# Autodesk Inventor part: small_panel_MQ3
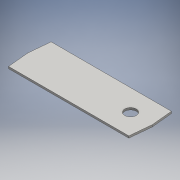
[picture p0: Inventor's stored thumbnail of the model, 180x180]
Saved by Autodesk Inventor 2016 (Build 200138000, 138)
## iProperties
Created: 2016-12
Part Number: small_panel_MQ3
Material: Типовые
Document SubType Name: Modeling
Designer: admin
Density: 1 g/cm^3
Appearance: По умолчанию
Author: admin
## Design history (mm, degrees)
sketch "Эскиз1"
  geometry: L1 (-89, -31.5)-(89, -31.5); L2 (89, 31.5)-(-89, 31.5); L3 (-89, 31.5)-(-92, 0); L4 (-92, 0)-(-89, -31.5); L5 (89, 31.5)-(92, 0); L6 (92, 0)-(89, -31.5); 3 further points
  constraints: 12 end point, 2 parallel, 1 coincident, 1 horizontal, 1 midpoint, 1 vertical alignment
extrude "Выдавливание1" new body sketch "Эскиз1" distance "d2" = 3; taper "d3" = 0 deg
sketch "Эскиз3"
  geometry: C1 r 8.5 at (60, 0); 1 further point
  constraints: 1 centre point
  dimensions: "d43" = 17 diameter of C1; "d44" = 60 distance of C1.centre point (0, 0)
extrude "Выдавливание3" cut sketch "Эскиз3" distance "d45" = 10; taper "d46" = 0 deg
node "Твердое тело1"
other parameters: "d7" = 15.6
